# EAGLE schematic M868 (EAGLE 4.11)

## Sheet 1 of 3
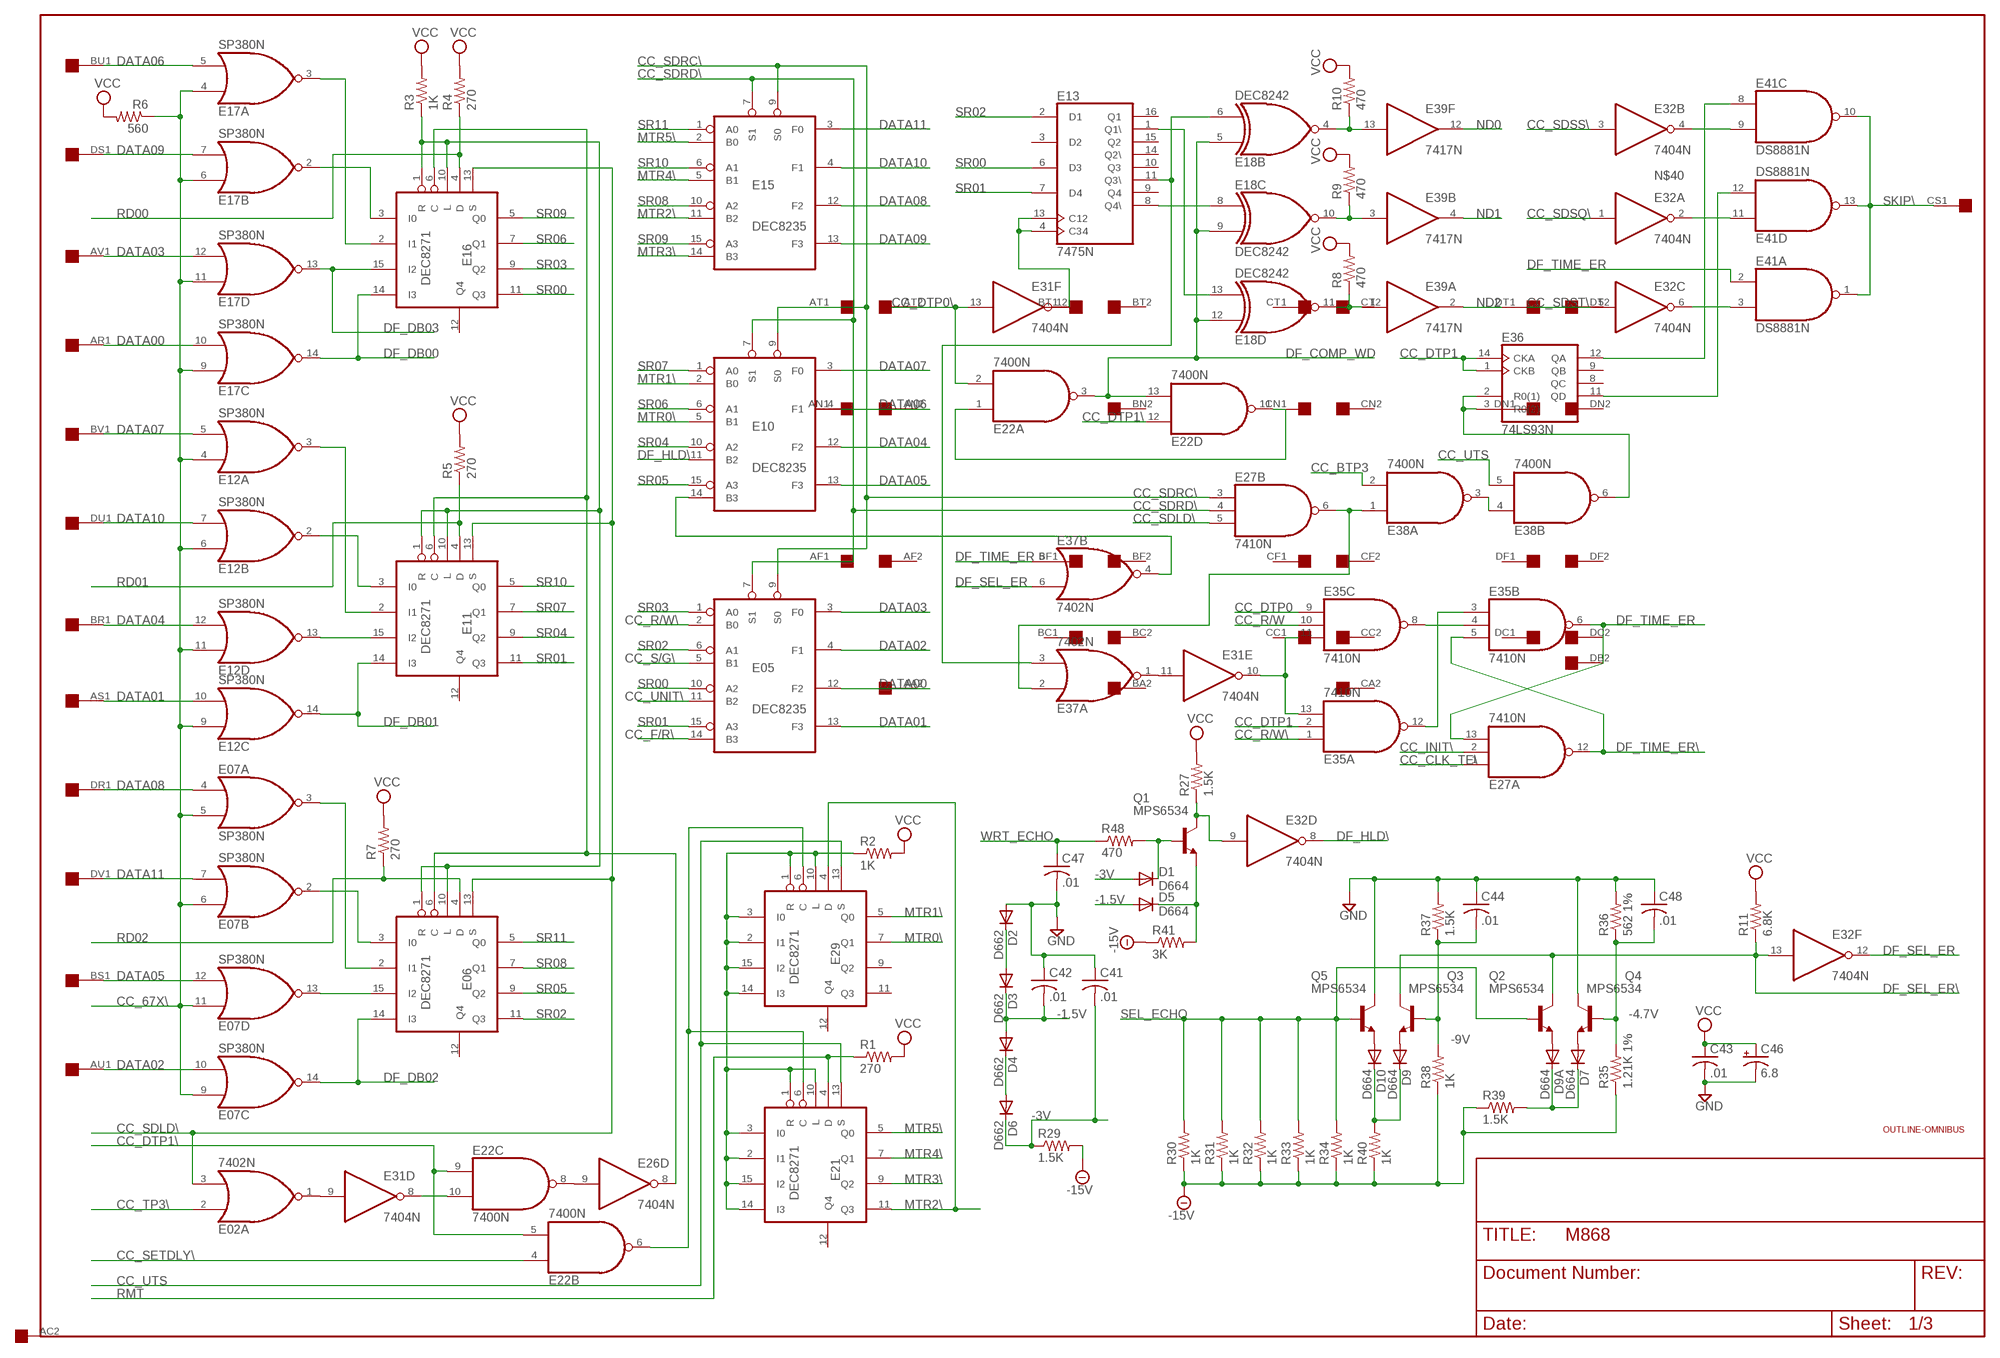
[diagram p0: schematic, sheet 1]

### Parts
C41  .01  C-US050-025X075  [C050-025X075]
C42  .01  C-US050-025X075  [C050-025X075]
C43  .01  C-US050-025X075  [C050-025X075]
C44  .01  C-US050-025X075  [C050-025X075]
C46  6.8  CPOL-USE22-6AXIAL  [E22-6]
C47  .01  C-US050-025X075  [C050-025X075]
C48  .01  C-US050-025X075  [C050-025X075]
D1  D664  1N4148  [DO35-10]
D2  D662  1N4148  [DO35-10]
D3  D662  1N4148  [DO35-10]
D4  D662  1N4148  [DO35-10]
D5  D664  1N4148  [DO35-10]
D6  D662  1N4148  [DO35-10]
D7  D664  1N4148  [DO35-10]
D9  D664  1N4148  [DO35-10]
D9A  D664  1N4148  [DO35-10]
D10  D664  1N4148  [DO35-10]
E02  7402N  [DIL14]
E05  DEC8235  [DIL16]
E06  DEC8271  [DIL16]
E07  SP380N  [DIL14]
E10  DEC8235  [DIL16]
E11  DEC8271  [DIL16]
E12  SP380N  [DIL14]
E13  7475N  [DIL16]
E15  DEC8235  [DIL16]
E16  DEC8271  [DIL16]
E17  SP380N  [DIL14]
E18  DEC8242  74LS266N  [DIL14]
E21  DEC8271  [DIL16]
E22  7400N  [DIL14]
E26  7404N  [DIL14]
E27  7410N  [DIL14]
E29  DEC8271  [DIL16]
E31  7404N  [DIL14]
E32  7404N  [DIL14]
E35  7410N  [DIL14]
E36  74LS93N  [DIL14]
E37  7402N  [DIL14]
E38  7400N  [DIL14]
E39  7417N  [DIL14]
E41  DS8881N  [DIL14]
EDGE$  QUAD  [EDGE-CON8]
Q1  MPS6534  2N2222  [TO18]
Q2  MPS6534  2N2222  [TO18]
Q3  MPS6534  2N2222  [TO18]
Q4  MPS6534  2N2222  [TO18]
Q5  MPS6534  2N2222  [TO18]
R1  270  R-US_0207/10  [0207/10]
R2  1K  R-US_0207/10  [0207/10]
R3  1K  R-US_0207/10  [0207/10]
R4  270  R-US_0207/10  [0207/10]
R5  270  R-US_0207/10  [0207/10]
R6  560  R-US_0207/10  [0207/10]
R7  270  R-US_0207/10  [0207/10]
R8  470  R-US_0207/10  [0207/10]
R9  470  R-US_0207/10  [0207/10]
R10  470  R-US_0207/10  [0207/10]
R11  6.8K  R-US_0207/10  [0207/10]
R27  1.5K  R-US_0207/10  [0207/10]
R29  1.5K  R-US_0207/10  [0207/10]
R30  1K  R-US_0207/10  [0207/10]
R31  1K  R-US_0207/10  [0207/10]
R32  1K  R-US_0207/10  [0207/10]
R33  1K  R-US_0207/10  [0207/10]
R34  1K  R-US_0207/10  [0207/10]
R35  1.21K 1%  R-US_0207/10  [0207/10]
R36  562 1%  R-US_0207/10  [0207/10]
R37  1.5K  R-US_0207/10  [0207/10]
R38  1K  R-US_0207/10  [0207/10]
R39  1.5K  R-US_0207/10  [0207/10]
R40  1K  R-US_0207/10  [0207/10]
R41  3K  R-US_0207/10  [0207/10]
R48  470  R-US_0207/10  [0207/10]
U$1  OUTLINE-OMNIBUS  [OMNIBUS]

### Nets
-1.5V: C42.2 D3.C D4.A D5.A
-3V: C41.2 D1.A D6.C R29.1
-4.7V: C48.2 Q4.2(B) R35.2 R36.1
-9V: C44.2 Q3.2(B) R37.1 R38.2
-15V [supply]: R29.2 R30.1 R31.1 R32.1 R33.1 R34.1 R35.1 R38.1 R39.1 R40.1 R41.1 ; also sheet 3
CC_67X\: E07.5(A:I1) E07.6(B:I0) E07.9(C:I0) E07.11(D:I0) E12.4(A:I0) E12.6(B:I0) E12.9(C:I0) E12.11(D:I0) E17.4(A:I0) E17.6(B:I0) E17.9(C:I0) E17.11(D:I0) R6.1 ; also sheet 2
CC_BTP3: E38.2(A:I1) ; also sheet 2
CC_CLK_TE\: E27.1(A:I0) ; also sheet 2
CC_DTP0: E35.9(C:I0) ; also sheet 2
CC_DTP0\: E22.2(A:I1) E31.13(F:I) ; also sheet 2
CC_DTP1: E35.2(A:I1) E36.1(CKB) E36.14(CKA) ; also sheet 2
CC_DTP1\: E22.5(B:I1) E22.9(C:I0) E22.12(D:I0) ; also sheet 2
CC_F/R\: E05.14(B3) ; also sheet 2
CC_INIT\: E27.2(A:I1) ; also sheet 2
CC_R/W: E35.10(C:I1) ; also sheet 2
CC_R/W\: E05.2(B0) E35.1(A:I0) ; also sheet 2
CC_S/G\: E05.5(B1) ; also sheet 2
CC_SDLD\: E02.3(A:I1) E06.13(S) E11.13(S) E16.13(S) E27.5(B:I2) ; also sheet 2
CC_SDRC\: E05.9(S0) E10.9(S0) E15.9(S0) E27.3(B:I0) ; also sheet 2
CC_SDRD\: E05.7(S1) E10.7(S1) E15.7(S1) E27.4(B:I1) ; also sheet 2
CC_SDSQ\: E32.1(A:I) ; also sheet 2
CC_SDSS\: E32.3(B:I) ; also sheet 2
CC_SDST\: E32.5(C:I) ; also sheet 2
CC_SETDLY\: E22.4(B:I0) ; also sheet 2
CC_TP3\: E02.2(A:I0) ; also sheet 2
CC_UNIT\: E05.11(B2) ; also sheet 2
CC_UTS: E21.13(S) E29.13(S) E38.5(B:I1) ; also sheet 2
DATA00: E05.12(F2) E17.10(C:I1) EDGE$.AR1
DATA01: E05.13(F3) E12.10(C:I1) EDGE$.AS1
DATA02: E05.4(F1) E07.10(C:I1) EDGE$.AU1
DATA03: E05.3(F0) E17.12(D:I1) EDGE$.AV1
DATA04: E10.12(F2) E12.12(D:I1) EDGE$.BR1
DATA05: E07.12(D:I1) E10.13(F3) EDGE$.BS1
DATA06: E10.4(F1) E17.5(A:I1) EDGE$.BU1
DATA07: E10.3(F0) E12.5(A:I1) EDGE$.BV1
DATA08: E07.4(A:I0) E15.12(F2) EDGE$.DR1
DATA09: E15.13(F3) E17.7(B:I1) EDGE$.DS1
DATA10: E12.7(B:I1) E15.4(F1) EDGE$.DU1
DATA11: E07.7(B:I1) E15.3(F0) EDGE$.DV1
DF_COMP_WD: E18.5(B:I0) E18.9(C:I1) E18.12(D:I0) E22.3(A:O) E22.13(D:I1)
DF_DB00: E16.14(I3) E17.14(C:O) ; also sheet 2
DF_DB01: E11.14(I3) E12.14(C:O) ; also sheet 2
DF_DB02: E06.14(I3) E07.14(C:O) ; also sheet 2
DF_DB03: E16.15(I2) E17.13(D:O) ; also sheet 2
DF_HLD\: E10.11(B2) E32.8(D:O) ; also sheet 2
DF_SEL_ER: E32.12(F:O) E37.6(B:I1)
DF_SEL_ER\: E32.13(F:I) Q2.3(C) Q3.3(C) R11.1 ; also sheet 2
DF_TIME_ER: E27.13(A:I2) E35.6(B:O) E37.5(B:I0) E41.2(A:I0)
DF_TIME_ER\: E27.12(A:O) E35.5(B:I2) ; also sheet 2
GND [supply]: C41.1 C42.1 C43.2 C44.1 C46.- C47.2 C48.1 D2.A Q4.3(C) Q5.3(C) R36.2 R37.2 ; also sheet 2,3
MTR0\: E10.5(B1) E29.7(Q1)
MTR1\: E10.2(B0) E29.5(Q0)
MTR2\: E15.11(B2) E21.11(Q3) E29.4(D)
MTR3\: E15.14(B3) E21.9(Q2)
MTR4\: E15.5(B1) E21.7(Q1)
MTR5\: E15.2(B0) E21.5(Q0)
N$1: E06.1(R) E06.10(L) E11.1(R) E11.10(L) E16.1(R) E16.10(L) R3.1
N$2: E02.1(A:O) E31.9(D:I)
N$3: E16.2(I1) E17.3(A:O)
N$4: E16.3(I0) E17.2(B:O)
N$5: E21.1(R) E21.2(I1) E21.3(I0) E21.10(L) E21.14(I3) E21.15(I2) E29.1(R) E29.2(I1) E29.3(I0) E29.10(L) E29.14(I3) E29.15(I2) R2.1
N$7: E06.6(C) E11.6(C) E16.6(C) E26.8(D:O)
N$8: E11.2(I1) E12.3(A:O)
N$9: E11.3(I0) E12.2(B:O)
N$11: E11.15(I2) E12.13(D:O)
N$13: E06.2(I1) E07.3(A:O)
N$14: E06.3(I0) E07.2(B:O)
N$16: E06.15(I2) E07.13(D:O)
N$22: E27.6(B:O) E37.2(A:I0) E38.1(A:I0)
N$25: E36.12(QA) E41.8(C:I0)
N$29: E22.8(C:O) E26.9(D:I)
N$30: E22.10(C:I1) E31.8(D:O)
N$31: E21.6(C) E22.6(B:O) E29.6(C)
N$32: E13.1(Q1\) E18.13(D:I1)
N$33: E18.11(D:O) E39.1(A:I) R8.1
N$34: E13.8(Q4\) E18.8(C:I0)
N$35: E13.4(C34) E13.13(C12) E31.12(F:O)
N$36: E13.11(Q3\) E18.6(B:I1) E37.3(A:I1)
N$37: E22.1(A:I0) E22.11(D:O)
N$38: E18.10(C:O) E39.3(B:I) R9.1
N$39: E18.4(B:O) E39.13(F:I) R10.1
N$40: E36.11(QD) E41.12(D:I1)
N$41: E10.14(B3) E37.4(B:O)
N$42: E36.2(R0(1)) E36.3(R0(2)) E38.6(B:O)
N$43: E38.3(A:O) E38.4(B:I0)
N$44: E32.6(C:O) E41.3(A:I1)
N$45: E32.2(A:O) E41.11(D:I0)
N$46: E32.4(B:O) E41.9(C:I1)
N$47: E31.11(E:I) E37.1(A:O)
N$48: E31.10(E:O) E35.11(C:I2) E35.13(A:I2)
N$49: E35.3(B:I0) E35.12(A:O)
N$50: E35.4(B:I1) E35.8(C:O)
N$51: D1.C Q1.2(B) R48.2
N$52: D5.C Q1.1(E) R41.2
N$53: E32.9(D:I) Q1.3(C) R27.1
N$54: D2.C D3.A
N$55: D9.C D10.C R40.2
N$56: D4.C D6.A
N$57: D10.A Q5.1(E)
N$58: D9.A Q3.1(E)
N$59: D9A.A Q2.1(E)
N$60: D7.A Q4.1(E)
N$63: D7.C D9A.C R39.2
ND0: E39.12(F:O) ; also sheet 3
ND1: E39.4(B:O) ; also sheet 3
ND2: E39.2(A:O) ; also sheet 3
RD00: E16.4(D) R4.1 ; also sheet 3
RD01: E11.4(D) R5.1 ; also sheet 3
RD02: E06.4(D) R7.1 ; also sheet 3
RMT: E21.4(D) R1.1 ; also sheet 3
SEL_ECHO: Q2.2(B) Q5.2(B) R30.2 R31.2 R32.2 R33.2 R34.2 ; also sheet 3
SKIP\: E41.1(A:O) E41.10(C:O) E41.13(D:O) EDGE$.CS1
SR00: E05.10(A2) E13.6(D3) E16.11(Q3)
SR01: E05.15(A3) E11.11(Q3) E13.7(D4)
SR02: E05.6(A1) E06.11(Q3) E13.2(D1)
SR03: E05.1(A0) E16.9(Q2)
SR04: E10.10(A2) E11.9(Q2)
SR05: E06.9(Q2) E10.15(A3)
SR06: E10.6(A1) E16.7(Q1)
SR07: E10.1(A0) E11.7(Q1)
SR08: E06.7(Q1) E15.10(A2)
SR09: E15.15(A3) E16.5(Q0)
SR10: E11.5(Q0) E15.6(A1)
SR11: E06.5(Q0) E15.1(A0)
VCC [supply]: C43.1 C46.+ R1.2 R2.2 R3.2 R4.2 R5.2 R6.2 R7.2 R8.2 R9.2 R10.2 R11.2 R27.2 ; also sheet 2,3
WRT_ECHO: C47.1 R48.1 ; also sheet 3
Unconnected: E06.12(Q4) E11.12(Q4) E13.3(D2) E13.9(Q4) E13.10(Q3) E13.14(Q2\) E13.15(Q2) E13.16(Q1) E16.12(Q4) E21.12(Q4) E29.9(Q2) E29.11(Q3) E29.12(Q4) E36.8(QC) E36.9(QB) E41.4(B:O) E41.5(B:I0) E41.6(B:I1) EDGE$.AA1 EDGE$.AB1 EDGE$.AB2 EDGE$.AC1 EDGE$.AD1 EDGE$.AD2 EDGE$.AE1 EDGE$.AE2 EDGE$.AH1 EDGE$.AH2 EDGE$.AJ1 EDGE$.AJ2 EDGE$.AK1 EDGE$.AK2 EDGE$.AL1 EDGE$.AL2 EDGE$.AM1 EDGE$.AM2 EDGE$.AP2 EDGE$.AR2 EDGE$.AS2 EDGE$.AU2 EDGE$.AV2 EDGE$.BA1 EDGE$.BB1 EDGE$.BB2 EDGE$.BD1 EDGE$.BD2 EDGE$.BE1 EDGE$.BE2 EDGE$.BH1 EDGE$.BH2 EDGE$.BJ1 EDGE$.BJ2 EDGE$.BK2 EDGE$.BL2 EDGE$.BM2 EDGE$.BN1 EDGE$.BP2 EDGE$.BR2 EDGE$.BS2 EDGE$.CA1 EDGE$.CB1 EDGE$.CB2 EDGE$.CD2 EDGE$.CE2 EDGE$.CJ1 EDGE$.CK1 EDGE$.CK2 EDGE$.CL2 EDGE$.CM1 EDGE$.CM2 EDGE$.CP1 EDGE$.CP2 EDGE$.CR2 EDGE$.CS2 EDGE$.CU1 EDGE$.CU2 EDGE$.CV1 EDGE$.CV2 EDGE$.DA1 EDGE$.DA2 EDGE$.DB1 EDGE$.DD1 EDGE$.DD2 EDGE$.DE1 EDGE$.DE2 EDGE$.DH1 EDGE$.DH2 EDGE$.DJ1 EDGE$.DJ2 EDGE$.DK2 EDGE$.DL2 EDGE$.DM2 EDGE$.DP2 EDGE$.DR2 EDGE$.DS2 EDGE$.DU2 EDGE$.DV2

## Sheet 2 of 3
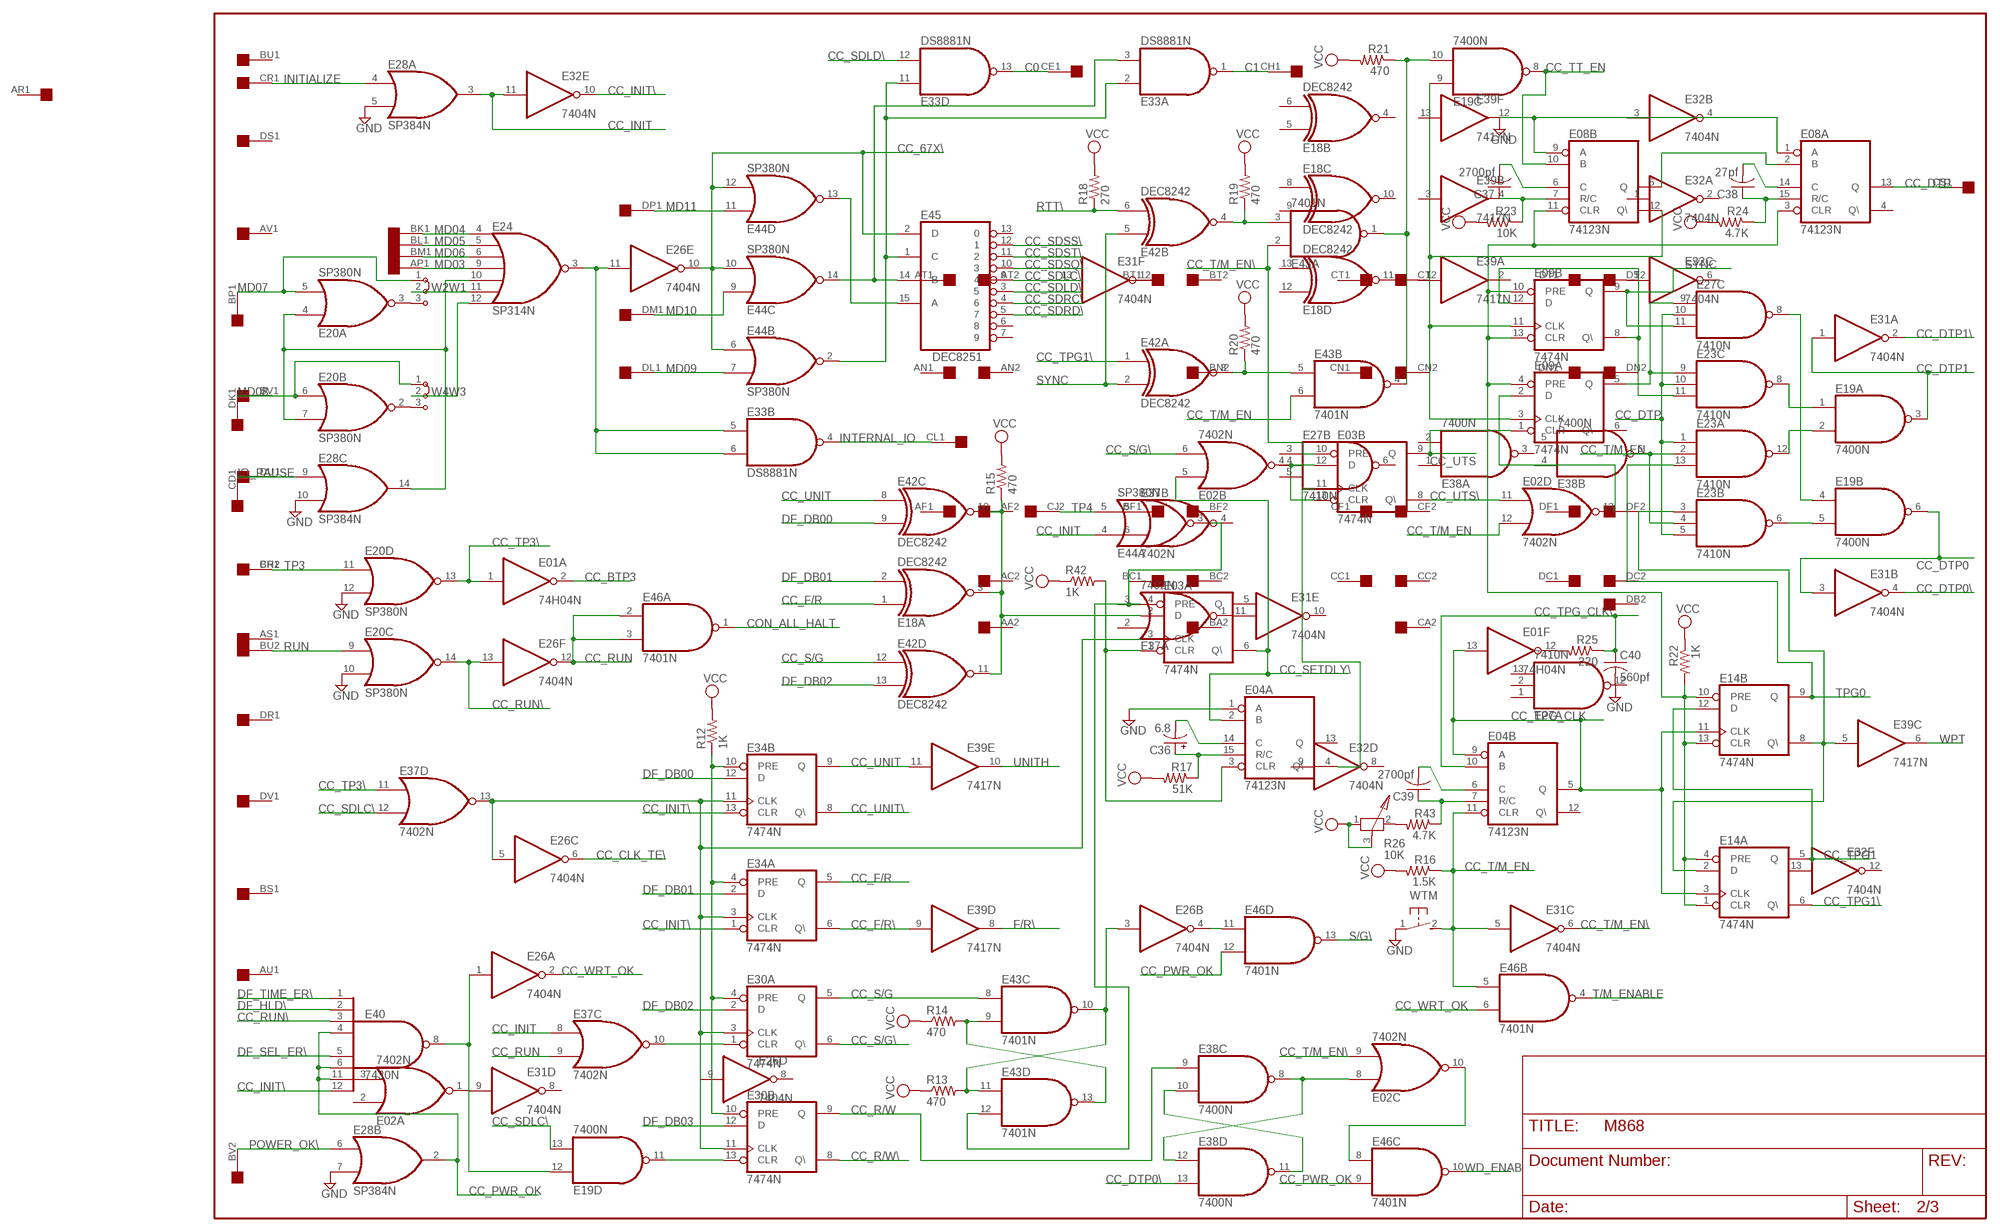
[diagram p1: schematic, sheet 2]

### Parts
C36  6.8  CPOL-USE22-6AXIAL  [E22-6]
C37  2700pf  C-US102-043X133  [C102-043X133]
C38  27pf  C-US050-025X075  [C050-025X075]
C39  2700pf  C-US102-043X133  [C102-043X133]
C40  560pf  C-US075-032X103  [C075-032X103]
E01  74H04N  74S04N  [DIL14]
E03  7474N  74S74N  [DIL14]
E04  74123N  [DIL16]
E08  74123N  [DIL16]
E09  7474N  74S74N  [DIL14]
E14  7474N  74S74N  [DIL14]
E19  7400N  [DIL14]
E20  SP380N  [DIL14]
E23  7410N  [DIL14]
E24  SP314N  [DIL14]
E28  SP384N  [DIL14]
E30  7474N  74S74N  [DIL14]
E33  DS8881N  [DIL14]
E34  7474N  74S74N  [DIL14]
E40  7430N  [DIL14]
E42  DEC8242  74LS266N  [DIL14]
E43  7401N  [DIL14]
E44  SP380N  [DIL14]
E45  DEC8251  [DIL16]
E46  7401N  [DIL14]
R12  1K  R-US_0207/10  [0207/10]
R13  470  R-US_0207/10  [0207/10]
R14  470  R-US_0207/10  [0207/10]
R15  470  R-US_0207/10  [0207/10]
R16  1.5K  R-US_0207/10  [0207/10]
R17  51K  R-US_0207/10  [0207/10]
R18  270  R-US_0207/10  [0207/10]
R19  470  R-US_0207/10  [0207/10]
R20  470  R-US_0207/10  [0207/10]
R21  470  R-US_0207/10  [0207/10]
R22  1K  R-US_0207/10  [0207/10]
R23  10K  R-US_0207/10  [0207/10]
R24  4.7K  R-US_0207/10  [0207/10]
R25  220  R-US_0207/10  [0207/10]
R26  10K  POT-TRIM  [PT-SPIN]
R42  1K  R-US_0207/10  [0207/10]
R43  4.7K  R-US_0207/10  [0207/10]
W2W1  J2X5MM  [05C]
W4W3  J2X5MM  [05C]
WTM  31-XX  [B3F-31XX]

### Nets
C0: E33.13(D:O) EDGE$.CE1
C1: E33.1(A:O) EDGE$.CH1
CC_67X: E24.3(O) E26.11(E:I) E33.5(B:I0) E33.6(B:I1)
CC_67X\: E26.10(E:O) E44.6(B:I0) E44.10(C:I1) E44.12(D:I1) E45.2(D) ; also sheet 1
CC_BTP3: E01.2(A:O) ; also sheet 1
CC_CLK_TE\: E26.6(C:O) ; also sheet 1
CC_DTP: E08.13(A:Q) E23.1(A:I0) E23.5(B:I2) E23.10(C:I1) E27.10(C:I1)
CC_DTP0: E19.6(B:O) E31.3(B:I) ; also sheet 1
CC_DTP0\: E31.4(B:O) E38.13(D:I1) ; also sheet 1
CC_DTP1: E19.3(A:O) E31.1(A:I) ; also sheet 1
CC_DTP1\: E31.2(A:O) ; also sheet 1
CC_F/R: E18.1(A:I0) E34.5(A:Q)
CC_F/R\: E34.6(A:Q\) E39.9(D:I) ; also sheet 1
CC_INIT: E28.3(A:O) E32.11(E:I) E37.8(C:I0) E44.4(A:I0)
CC_INIT\: E32.10(E:O) E34.1(A:CLR) E34.13(B:CLR) E40.12(I7) ; also sheet 1
CC_PWR_OK: E28.2(B:O) E40.4(I3) E40.6(I5) E40.11(I6) E46.9(C:I1) E46.12(D:I1)
CC_R/W: E30.9(B:Q) E38.9(C:I0) ; also sheet 1
CC_R/W\: E30.8(B:Q\) ; also sheet 1
CC_RUN: E26.12(F:O) E37.9(C:I1) E46.2(A:I0) E46.3(A:I1)
CC_RUN\: E20.14(C:O) E26.13(F:I) E40.3(I2)
CC_S/G: E30.5(A:Q) E42.12(D:I0) E43.8(C:I0)
CC_S/G\: E02.6(B:I1) E30.6(A:Q\) ; also sheet 1
CC_SDLC\: E19.13(D:I1) E37.12(D:I1) E45.9
CC_SDLD\: E33.12(D:I1) E45.3 ; also sheet 1
CC_SDRC\: E45.4 ; also sheet 1
CC_SDRD\: E45.5 ; also sheet 1
CC_SDSQ\: E45.10 ; also sheet 1
CC_SDSS\: E45.12 ; also sheet 1
CC_SDST\: E45.11 ; also sheet 1
CC_SETDLY\: E02.5(B:I0) E03.6(A:Q\) E04.2(A:B) ; also sheet 1
CC_T/M_EN: E02.12(D:I1) E04.11(B:CLR) E23.2(A:I1) E23.4(B:I1) E31.5(C:I) E43.6(B:I1) E46.5(B:I0) R16.1 WTM.2(S)
CC_T/M_EN\: E02.9(C:I1) E03.10(B:PRE) E31.6(C:O) E43.2(A:I0)
CC_TP3\: E01.1(A:I) E20.13(D:O) E37.11(D:I0) ; also sheet 1
CC_TPG1: E14.5(A:Q) E14.12(B:D)
CC_TPG1\: E14.6(A:Q\) E42.1(A:I0)
CC_TPG_CLK: E01.13(F:I) E04.5(B:Q) E04.9(B:A) E14.3(A:CLK) E14.11(B:CLK)
CC_TPG_CLK\: C40.1 E04.10(B:B) R25.1
CC_TT_EN: E08.10(B:B) E19.8(C:O)
CC_UNIT: E34.9(B:Q) E39.11(E:I) E42.8(C:I0)
CC_UNIT\: E34.8(B:Q\) ; also sheet 1
CC_UTS: E03.9(B:Q) E09.1(A:CLR) ; also sheet 1
CC_UTS\: E02.11(D:I0) E03.8(B:Q\)
CC_WRT_OK: E26.2(A:O) E46.6(B:I1)
CON_ALL_HALT: E46.1(A:O) ; also sheet 3
DF_DB00: E34.12(B:D) E42.9(C:I1) ; also sheet 1
DF_DB01: E18.2(A:I1) E34.2(A:D) ; also sheet 1
DF_DB02: E30.2(A:D) E42.13(D:I1) ; also sheet 1
DF_DB03: E30.12(B:D) ; also sheet 1
DF_HLD\: E40.2(I1) ; also sheet 1
DF_SEL_ER\: E40.5(I4) ; also sheet 1
DF_TIME_ER\: E40.1(I0) ; also sheet 1
F/R\: E39.8(D:O) ; also sheet 3
GND [supply]: C40.2 E04.1(A:A) E08.1(A:A) E08.9(B:A) E20.10(C:I1) E20.12(D:I1) E28.5(A:I1) E28.7(B:I1) E28.10(C:I1) WTM.1(P) ; also sheet 1,3
INITIALIZE: E28.4(A:I0) EDGE$.CR1
INTERNAL_IO: E33.4(B:O) EDGE$.CL1
IO_PAUSE: E28.9(C:I0) EDGE$.CD1
IO_PAUSE\: E20.4(A:I0) E20.7(B:I1) E24.10(I4) E28.14(C:O)
MD03: E24.9(I3) EDGE$.AP1
MD04: E24.4(I0) EDGE$.BK1
MD05: E24.5(I1) EDGE$.BL1
MD06: E24.6(I2) EDGE$.BM1
MD07: E20.5(A:I1) EDGE$.BP1 W2W1.1
MD08: E20.6(B:I0) EDGE$.DK1 W4W3.1
MD09: E44.7(B:I1) EDGE$.DL1
MD10: E44.9(C:I0) EDGE$.DM1
MD11: E44.11(D:I0) EDGE$.DP1
N$6: E43.9(C:I1) E43.13(D:O) R14.2
N$17: E08.3(A:CLR) E08.11(B:CLR) E09.4(A:PRE) E09.10(B:PRE) E09.13(B:CLR) E14.1(A:CLR) E14.4(A:PRE) E14.10(B:PRE) E14.13(B:CLR) R22.2
N$18: E30.1(A:CLR) E37.10(C:O)
N$20: E26.3(B:I) E43.10(C:O) E43.11(D:I0) R13.2
N$61: E24.11(I5) W2W1.2
N$62: E24.12(I6) W4W3.2
N$65: E20.3(A:O) W2W1.3
N$66: E19.12(D:I0) E26.1(A:I) E40.8(O)
N$67: E20.2(B:O) W4W3.3
N$68: E19.11(D:O) E30.13(B:CLR)
N$69: E33.2(A:I0) E33.11(D:I0) E44.2(B:O) E45.1(C)
N$70: E33.3(A:I1) E44.14(C:O) E45.14(B)
N$71: E44.13(D:O) E45.15(A)
N$72: E42.4(B:O) E43.3(A:I1) R19.1
N$73: E19.10(C:I1) E43.1(A:O) E43.4(B:O) R21.1
N$74: E42.3(A:O) E43.5(B:I0) R20.1
N$77: E08.2(A:B) E08.5(B:Q)
N$78: C37.1 E08.7(B:R/C) R23.1
N$79: C38.1 E08.15(A:R/C) R24.1
N$80: E08.12(B:Q\) E09.3(A:CLK) E09.11(B:CLK) E19.9(C:I0)
N$81: C38.2 E08.14(A:C)
N$82: C37.2 E08.6(B:C)
N$83: E03.3(A:CLK) E26.5(C:I) E30.3(A:CLK) E30.11(B:CLK) E34.3(A:CLK) E34.11(B:CLK) E37.13(D:O)
N$84: E30.4(A:PRE) E30.10(B:PRE) E34.4(A:PRE) E34.10(B:PRE) R12.1
N$85: E38.10(C:I1) E38.11(D:O)
N$86: E02.8(C:I0) E38.8(C:O) E38.12(D:I0)
N$87: E03.4(A:PRE) E43.12(D:I1) E44.3(A:O)
N$88: E26.4(B:O) E46.11(D:I0)
N$89: E02.10(C:O) E46.8(C:I0)
N$90: E03.2(A:D) E18.3(A:O) E42.10(C:O) E42.11(D:O) R15.1
N$92: E03.1(A:CLR) E04.3(A:CLR) R42.2
N$94: C36.+ E04.15(A:R/C) R17.1
N$95: C36.- E04.14(A:C)
N$96: E03.11(B:CLK) E04.4(A:Q\)
N$97: E02.4(B:O) E03.12(B:D) E03.13(B:CLR)
N$98: E02.13(D:O) E09.2(A:D)
N$100: E19.5(B:I1) E23.6(B:O)
N$101: E09.5(A:Q) E23.9(C:I0) E27.9(C:I0)
N$102: E09.8(B:Q\) E09.12(B:D) E23.11(C:I2)
N$104: E19.2(A:I1) E23.12(A:O)
N$106: E19.1(A:I0) E23.8(C:O)
N$107: E14.2(A:D) E14.8(B:Q\) E23.3(B:I0) E39.5(C:I)
N$108: C39.1 E04.7(B:R/C) R43.1
N$109: E19.4(B:I0) E27.8(C:O)
N$110: C39.2 E04.6(B:C)
N$111: R26.2 R43.2
N$112: E01.12(F:O) R25.2
POWER_OK\: E28.6(B:I0) EDGE$.BV2
RTT\: E42.6(B:I1) R18.1 ; also sheet 3
RUN: E20.9(C:I0) EDGE$.BU2
S/G\: E46.13(D:O) ; also sheet 3
SYNC: E09.9(B:Q) E27.11(C:I2) E42.2(A:I1) E42.5(B:I0)
T/M_ENABLE: E46.4(B:O) ; also sheet 3
TP3: E20.11(D:I0) EDGE$.CH2
TP4: E44.5(A:I1) EDGE$.CJ2
TPG0: E14.9(B:Q) E23.13(A:I2)
UNITH: E39.10(E:O) ; also sheet 3
VCC [supply]: R12.2 R13.1 R14.1 R15.2 R16.2 R17.2 R18.2 R19.2 R20.2 R21.2 R22.1 R23.2 R24.2 R26.1 R26.3 R42.1 ; also sheet 1,3
WD_ENAB: E46.10(C:O) ; also sheet 3
WPT: E39.6(C:O) ; also sheet 3
Unconnected: E01.3(B:I) E01.4(B:O) E01.5(C:I) E01.6(C:O) E01.8(D:O) E01.9(D:I) E01.10(E:O) E01.11(E:I) E03.5(A:Q) E04.12(B:Q\) E04.13(A:Q) E08.4(A:Q\) E09.6(A:Q\) E28.11(D:I0) E28.12(D:I1) E28.13(D:O) E33.8(C:I0) E33.9(C:I1) E33.10(C:O) E45.6 E45.7 E45.13

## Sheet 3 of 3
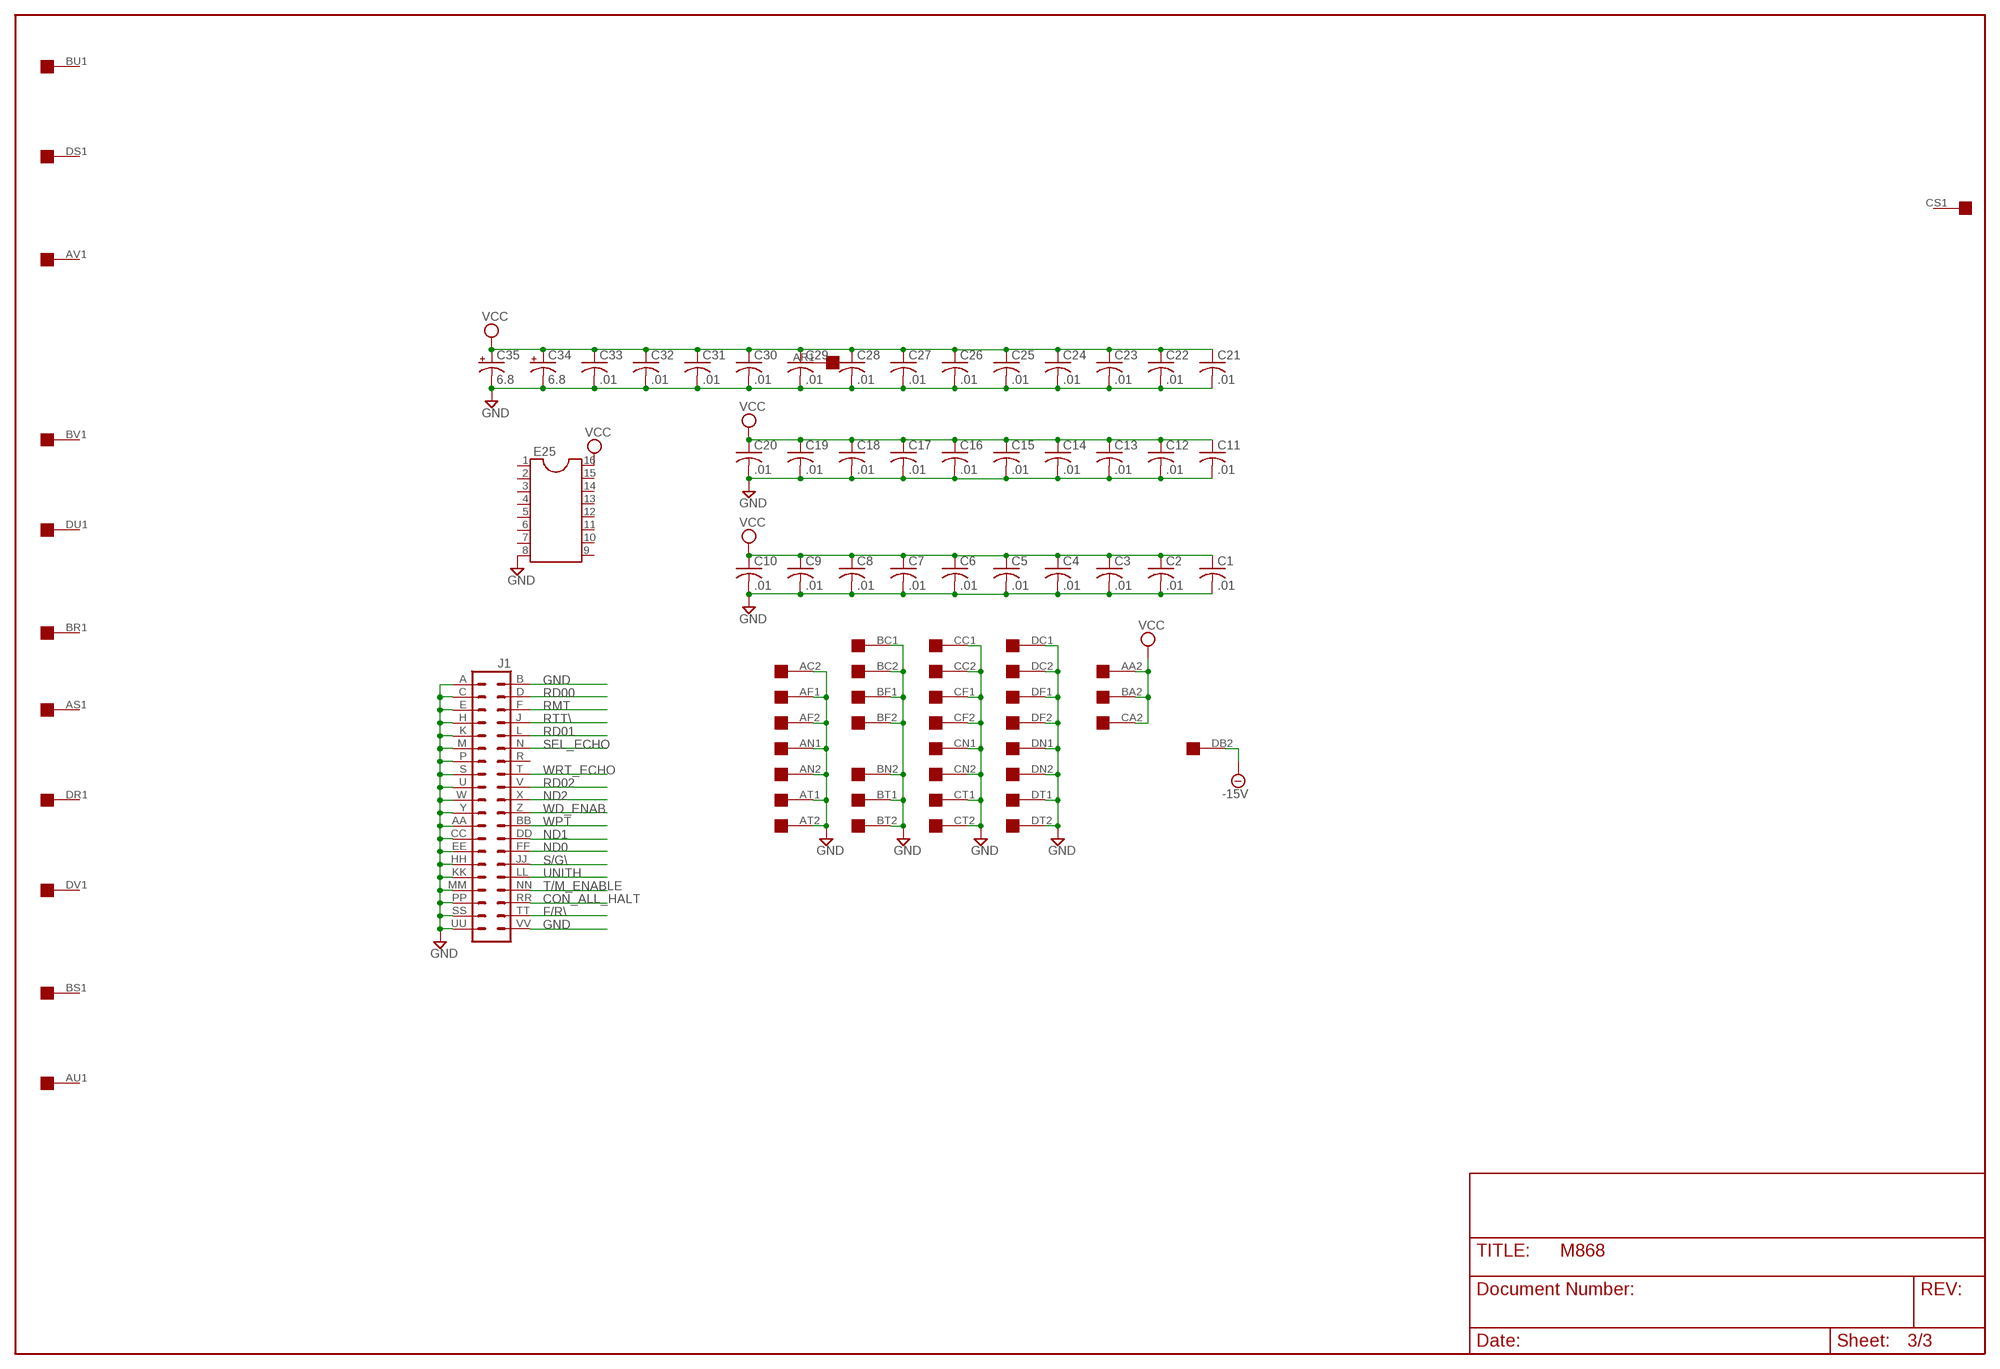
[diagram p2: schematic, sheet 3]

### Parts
C1  .01  C-US050-025X075  [C050-025X075]
C2  .01  C-US050-025X075  [C050-025X075]
C3  .01  C-US050-025X075  [C050-025X075]
C4  .01  C-US050-025X075  [C050-025X075]
C5  .01  C-US050-025X075  [C050-025X075]
C6  .01  C-US050-025X075  [C050-025X075]
C7  .01  C-US050-025X075  [C050-025X075]
C8  .01  C-US050-025X075  [C050-025X075]
C9  .01  C-US050-025X075  [C050-025X075]
C10  .01  C-US050-025X075  [C050-025X075]
C11  .01  C-US050-025X075  [C050-025X075]
C12  .01  C-US050-025X075  [C050-025X075]
C13  .01  C-US050-025X075  [C050-025X075]
C14  .01  C-US050-025X075  [C050-025X075]
C15  .01  C-US050-025X075  [C050-025X075]
C16  .01  C-US050-025X075  [C050-025X075]
C17  .01  C-US050-025X075  [C050-025X075]
C18  .01  C-US050-025X075  [C050-025X075]
C19  .01  C-US050-025X075  [C050-025X075]
C20  .01  C-US050-025X075  [C050-025X075]
C21  .01  C-US050-025X075  [C050-025X075]
C22  .01  C-US050-025X075  [C050-025X075]
C23  .01  C-US050-025X075  [C050-025X075]
C24  .01  C-US050-025X075  [C050-025X075]
C25  .01  C-US050-025X075  [C050-025X075]
C26  .01  C-US050-025X075  [C050-025X075]
C27  .01  C-US050-025X075  [C050-025X075]
C28  .01  C-US050-025X075  [C050-025X075]
C29  .01  C-US050-025X075  [C050-025X075]
C30  .01  C-US050-025X075  [C050-025X075]
C31  .01  C-US050-025X075  [C050-025X075]
C32  .01  C-US050-025X075  [C050-025X075]
C33  .01  C-US050-025X075  [C050-025X075]
C34  6.8  CPOL-USE22-6AXIAL  [E22-6]
C35  6.8  CPOL-USE22-6AXIAL  [E22-6]
E25  DIL16  [DIL16]
J1  DEC40PINH  [DEC40PINH]

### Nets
-15V [supply]: EDGE$.DB2 ; also sheet 1
CON_ALL_HALT: J1.RR ; also sheet 2
F/R\: J1.TT ; also sheet 2
GND [supply]: C1.2 C2.2 C3.2 C4.2 C5.2 C6.2 C7.2 C8.2 C9.2 C10.2 C11.2 C12.2 C13.2 C14.2 C15.2 C16.2 C17.2 C18.2 C19.2 C20.2 C21.2 C22.2 C23.2 C24.2 C25.2 C26.2 C27.2 C28.2 C29.2 C30.2 C31.2 C32.2 C33.2 C34.- C35.- E25.8 EDGE$.AC2 EDGE$.AF1 EDGE$.AF2 EDGE$.AN1 EDGE$.AN2 EDGE$.AT1 EDGE$.AT2 EDGE$.BC1 EDGE$.BC2 EDGE$.BF1 EDGE$.BF2 EDGE$.BN2 EDGE$.BT1 EDGE$.BT2 EDGE$.CC1 EDGE$.CC2 EDGE$.CF1 EDGE$.CF2 EDGE$.CN1 EDGE$.CN2 EDGE$.CT1 EDGE$.CT2 EDGE$.DC1 EDGE$.DC2 EDGE$.DF1 EDGE$.DF2 EDGE$.DN1 EDGE$.DN2 EDGE$.DT1 EDGE$.DT2 J1.A J1.AA J1.B J1.C J1.CC J1.E J1.EE J1.H J1.HH J1.K J1.KK J1.M J1.MM J1.P J1.PP J1.S J1.SS J1.U J1.UU J1.VV J1.W J1.Y ; also sheet 1,2
ND0: J1.FF ; also sheet 1
ND1: J1.DD ; also sheet 1
ND2: J1.X ; also sheet 1
RD00: J1.D ; also sheet 1
RD01: J1.L ; also sheet 1
RD02: J1.V ; also sheet 1
RMT: J1.F ; also sheet 1
RTT\: J1.J ; also sheet 2
S/G\: J1.JJ ; also sheet 2
SEL_ECHO: J1.N ; also sheet 1
T/M_ENABLE: J1.NN ; also sheet 2
UNITH: J1.LL ; also sheet 2
VCC [supply]: C1.1 C2.1 C3.1 C4.1 C5.1 C6.1 C7.1 C8.1 C9.1 C10.1 C11.1 C12.1 C13.1 C14.1 C15.1 C16.1 C17.1 C18.1 C19.1 C20.1 C21.1 C22.1 C23.1 C24.1 C25.1 C26.1 C27.1 C28.1 C29.1 C30.1 C31.1 C32.1 C33.1 C34.+ C35.+ E25.16 EDGE$.AA2 EDGE$.BA2 EDGE$.CA2 ; also sheet 1,2
WD_ENAB: J1.Z ; also sheet 2
WPT: J1.BB ; also sheet 2
WRT_ECHO: J1.T ; also sheet 1
Unconnected: E25.1 E25.2 E25.3 E25.4 E25.5 E25.6 E25.7 E25.9 E25.10 E25.11 E25.12 E25.13 E25.14 E25.15 J1.R

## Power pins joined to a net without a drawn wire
GND: E01.7(P:GND) E02.7(P:GND) E03.7(P:GND) E04.8(P:GND) E05.8(GND) E06.8(GND) E07.1(P:GND) E08.8(P:GND) E09.7(P:GND) E10.8(GND) E11.8(GND) E12.1(P:GND) E13.12(GND) E14.7(P:GND) E15.8(GND) E16.8(GND) E17.1(P:GND) E18.7(P:GND) E19.7(P:GND) E20.1(P:GND) E21.8(GND) E22.7(P:GND) E23.7(P:GND) E24.7(GND) E26.7(P:GND) E27.7(P:GND) E28.1(GND) E29.8(GND) E30.7(P:GND) E31.7(P:GND) E32.7(P:GND) E33.7(P:GND) E34.7(P:GND) E35.7(P:GND) E36.10(GND) E37.7(P:GND) E38.7(P:GND) E39.7(P:GND) E40.7(GND) E41.7(P:GND) E42.7(P:GND) E43.7(P:GND) E44.1(P:GND) E45.8(GND) E46.7(P:GND)
VCC: E01.14(P:VCC) E02.14(P:VCC) E03.14(P:VCC) E04.16(P:VCC) E05.16(VCC) E06.16(VCC) E07.8(P:VCC) E08.16(P:VCC) E09.14(P:VCC) E10.16(VCC) E11.16(VCC) E12.8(P:VCC) E13.5(VCC) E14.14(P:VCC) E15.16(VCC) E16.16(VCC) E17.8(P:VCC) E18.14(P:VCC) E19.14(P:VCC) E20.8(P:VCC) E21.16(VCC) E22.14(P:VCC) E23.14(P:VCC) E24.14(VCC) E26.14(P:VCC) E27.14(P:VCC) E28.8(VCC) E29.16(VCC) E30.14(P:VCC) E31.14(P:VCC) E32.14(P:VCC) E33.14(P:VCC) E34.14(P:VCC) E35.14(P:VCC) E36.5(VCC) E37.14(P:VCC) E38.14(P:VCC) E39.14(P:VCC) E40.14(VCC) E41.14(P:VCC) E42.14(P:VCC) E43.14(P:VCC) E44.8(P:VCC) E45.16(VCC) E46.14(P:VCC)

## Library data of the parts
C1-C33 C37-C44 C47 C48 = rcl:C-US: CAPACITOR, American symbol
C34-C36 C46 = rcl:CPOL-US: POLARIZED CAPACITOR, American symbol
D1-D7 D9 D9A D10 = diode:1N4148: DIODE
E01 E26 E31 E32 = 74xx-jameco:74*04: Hex INVERTER
E02 E37 = 74xx-jameco:74*02: Quad 2-input NOR gate
E03 E09 E14 E30 E34 = 74xx-jameco:74*74: Dual D type positive edge triggered FLIP FLOP, preset and clear
E04 E08 = 74xx-jameco:74*123: Retriggerable monostable MULTIVIBRATOR
E05 E10 E15 = dec-con:DEC8235: 4-bit data selector
E06 E11 E16 E21 E29 = dec-con:DEC8271: Parallel Load Shift Register
E07 E12 E17 E20 E44 = dec-con:SP380: Quad NOR gate (use 8640)
E13 = 74xx-jameco:74*75: 4-bit bistable LATCH
E18 E42 = 74xx-jameco:74*266: Quadruple EXCLUSIVE-NOR (XNOR), open-collector
E19 E22 E38 = 74xx-jameco:74*00: Quad 2-input NAND gate
E23 E27 E35 = 74xx-jameco:74*10: Triple 3-input NAND gate
E24 = dec-con:SP314: 7-Input NOR gate
E25 = ic-package:DIL16: Dual In Line
E28 = dec-con:SP384: Quad OR gate
E33 E41 = dec-con:DS8881: Quad 2-input NAND gate, open collector
E36 = 74xx-jameco:74*93: Decade, divide by twelve and binary COUNTER
E39 = 74xx-eu:74*17: Hex open collector, high-voltage
E40 = 74xx-jameco:74*30: 8-input NAND gate
E43 E46 = 74xx-jameco:74*01: Quad 2-input NAND gate, open collector
E45 = dec-con:DEC8251: BCD Decoder
EDGE$ = dec-con:QUAD: Quad-Height DEC board
J1 = dec-con:DEC40PIN: PIN HEADER
Q1-Q5 = transistor:2N2222: NPN TRANSISTOR
R1-R25 R27 R29-R43 R48 = rcl:R-US_: RESISTOR, American symbol
R26 = discrete:POT-TRIM
U$1 = dec-con:OUTLINE-*: Board outlines for DEC boards.
W2W1 W4W3 = jumper:J2: Jumper switch 2 x 2.5 mm
WTM = switch-omron:31-XX: OMRON SWITCH

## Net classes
1 supply: width 0.635 mm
